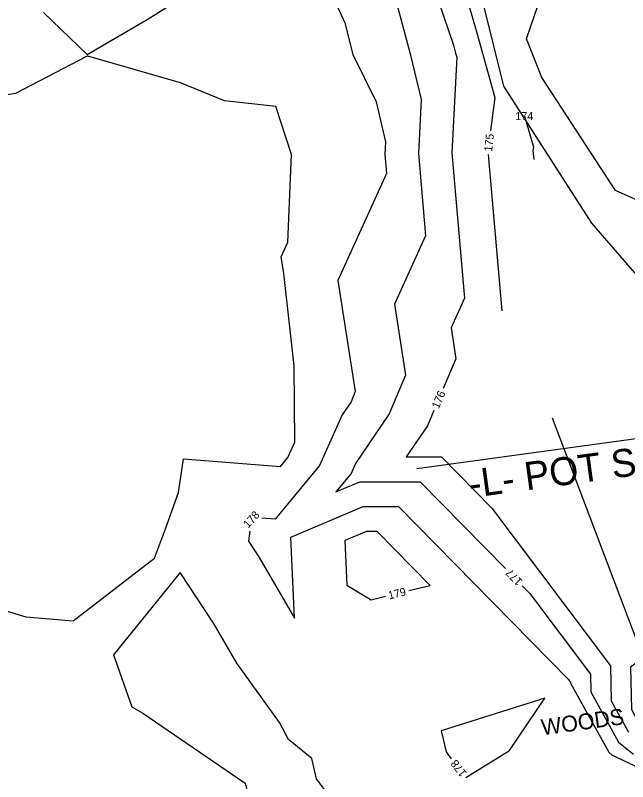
# Model space of a CAD drawing. Extents: x 2086416 to 2115205, y 575507 to 632762.
# Drawn here: x 2111202.3 to 2111355.3, y 581693.6 to 581885 of the extents above; entities that cross this region are included whole.
import ezdxf

# ---------------------------------------------------------------- set-up
doc = ezdxf.new("R2010")
doc.units = 0
for name, color, linetype in [('DTM Contours Major', 7, 'Continuous'), ('DTM Contours Major Text', 7, 'Continuous'), ('DTM Contours Minor', 7, 'Continuous'), ('DTM Contours Minor Text', 7, 'Continuous'), ('Exist Hydro Stream or Body of Water', 7, 'Continuous'), ('Exist Vegetation Woods Line', 7, 'Continuous'), ('Exist Vegetation Woods Line Text', 7, 'Continuous'), ('Prop Horizontal Alignment Station Label', 7, 'Continuous')]:
    doc.layers.add(name, color=color, linetype=linetype)

msp = doc.modelspace()

# ---------------------------------------------------------------- linework, layer by layer
at = {"layer": 'DTM Contours Major'}
for points in [[(2111294.42, 581951.65), (2111302.04, 581927.39), (2111305.43, 581920.13), (2111306.86, 581913.39), (2111309.95, 581907.16), (2111317.63, 581880.63), (2111322.13, 581864.47), (2111321.07, 581856.22)], [(2111320.43, 581850.26), (2111323.88, 581811.2)], [(2111336.48, 581784.42), (2111359.19, 581724.48), (2111356.03, 581722.18), (2111356.22, 581711.58), (2111357.93, 581708.49), (2111367.42, 581700.82), (2111367.7, 581700.69), (2111370.5, 581699.17), (2111370.16, 581701.31)]]:
    msp.add_lwpolyline(points, dxfattribs=at)
at = {"layer": 'DTM Contours Minor'}
for points in [[(2111267.74, 581979.73), (2111268.68, 581977.35), (2111273.87, 581968.84), (2111278.26, 581965.37), (2111287.18, 581945.83), (2111288.13, 581942.79), (2111297.45, 581922.87), (2111301.36, 581904.36), (2111305.53, 581895.97), (2111311.8, 581877.57), (2111312.33, 581875.57), (2111312.59, 581874.51), (2111311.38, 581850.65), (2111314.56, 581814.31), (2111311.18, 581806.9), (2111312.39, 581799.22), (2111309.24, 581791.82)], [(2111255.12, 581935.83), (2111260.16, 581925.24), (2111262.37, 581919.63), (2111267.2, 581916.59), (2111274.77, 581907.52), (2111277.54, 581898.66), (2111284.66, 581883.15), (2111286.66, 581875.21), (2111292.46, 581863.42), (2111294.84, 581853.39), (2111294.68, 581850.26), (2111295.1, 581845.49), (2111282.89, 581818.74), (2111287.27, 581791.01), (2111286.2, 581788.48), (2111283.99, 581785.23), (2111278.31, 581772.53), (2111267.27, 581759.11), (2111263.91, 581759.38)], [(2111268.74, 581824.66), (2111270.41, 581828.31), (2111271.33, 581850.23), (2111267.38, 581862.23), (2111254.62, 581863.65), (2111243.58, 581868.14), (2111220.45, 581874.8), (2111220.28, 581874.83), (2111202.41, 581865.47), (2111192.71, 581863.81), (2111182.9, 581866.81), (2111168.35, 581871.46), (2111157.17, 581875.34), (2111163.3, 581887.8), (2111160.57, 581900.16), (2111168.13, 581917.03)], [(2111292.27, 581905.43), (2111295.25, 581895.93), (2111295.93, 581894.45), (2111301, 581875.36), (2111303.71, 581863.95), (2111303.03, 581850.45), (2111304.83, 581829.9), (2111297.03, 581812.82), (2111299.83, 581795.12), (2111295.74, 581785.49), (2111287.34, 581773.08), (2111286.2, 581770.54), (2111282.44, 581765.97), (2111288.39, 581768.49), (2111303.45, 581768.49), (2111324.76, 581746.78)], [(2111209.35, 581885.74), (2111220.29, 581875.21), (2111235.29, 581883.96), (2111244.87, 581890.06), (2111253.08, 581891.47), (2111248.89, 581899.98), (2111246.81, 581901.29)], [(2111329.52, 581859.82), (2111331.49, 581853), (2111331.75, 581852.06), (2111331.65, 581851.26), (2111331.85, 581848.95)], [(2111172.65, 581747.61), (2111175.49, 581739.43), (2111189.76, 581746.49), (2111199.26, 581736.52), (2111204.94, 581734.72), (2111216.79, 581733.74), (2111237.11, 581749.36), (2111239.88, 581756.72), (2111243.14, 581765.77), (2111244.32, 581774.22), (2111268.57, 581772.28), (2111270.42, 581774.52), (2111272.15, 581778.4), (2111272.02, 581797.41), (2111269.39, 581820.52), (2111268.74, 581824.66)], [(2111306.89, 581786.29), (2111305.27, 581782.49), (2111300, 581774.7), (2111308.81, 581774.7), (2111321.39, 581761.89), (2111351, 581722.5), (2111351.15, 581713.78), (2111355.49, 581705.96)], [(2111260.91, 581756.14), (2111260.56, 581753.66), (2111263.25, 581749.57), (2111272.06, 581734.37), (2111271.17, 581754.63), (2111289.23, 581762.28), (2111298.09, 581762.28), (2111340.41, 581719.17), (2111341.02, 581718.36), (2111341.03, 581718.18), (2111350.61, 581700.9), (2111351.45, 581700.22), (2111365.39, 581693.62), (2111366.1, 581693.23), (2111372.81, 581687.77), (2111373.33, 581687.33), (2111373.12, 581686.65), (2111370.29, 581684.39), (2111374.42, 581679.53), (2111381.41, 581682.41)], [(2111292.74, 581756.06), (2111290.08, 581756.06), (2111284.68, 581753.78), (2111285.16, 581742.69), (2111291.22, 581739.02), (2111294.81, 581739.88)], [(2111300.64, 581741.29), (2111305.98, 581742.58), (2111292.74, 581756.06)], [(2111252.01, 581732.92), (2111243.5, 581745.85), (2111226.88, 581725.22), (2111231.48, 581712.27), (2111234.2, 581710.64), (2111259.76, 581693.18), (2111261.75, 581685.36), (2111258.49, 581673.26), (2111269.36, 581662.09), (2111244.24, 581668.39), (2111243.94, 581670.7), (2111236.21, 581669.26), (2111222.87, 581667.9), (2111221.36, 581667.61), (2111219.89, 581666.65), (2111218.75, 581661.3), (2111218.6, 581660), (2111219.79, 581657.23), (2111220.12, 581657.16), (2111220.04, 581657.09), (2111221.26, 581655.77), (2111227.78, 581651.56), (2111229.17, 581651.62)], [(2111328.97, 581742.5), (2111330.9, 581740.53), (2111346.01, 581720.43), (2111346.09, 581715.98), (2111353.05, 581703.43), (2111356.77, 581700.42)], [(2111235.16, 581651.86), (2111248.8, 581652.41), (2111249.48, 581653.23), (2111270, 581661.14), (2111270.74, 581661.11), (2111272.17, 581661.2), (2111281.87, 581666.23), (2111283.35, 581675.5), (2111281.36, 581689.25), (2111277.59, 581694.27), (2111276.39, 581699.32), (2111270.55, 581704.07), (2111268.32, 581708.33), (2111257.68, 581723.13), (2111252.01, 581732.92)], [(2111334.62, 581714.44), (2111308.74, 581706.23), (2111309.97, 581701), (2111311.25, 581699.31)], [(2111314.86, 581694.57), (2111325.77, 581701.36), (2111334.62, 581714.44)]]:
    msp.add_lwpolyline(points, dxfattribs=at)
at = {"layer": 'Exist Hydro Stream or Body of Water'}
msp.add_lwpolyline([(2111463, 581737.48), (2111415.11, 581766.53), (2111397.64, 581820.96), (2111352.3, 581841.23), (2111333.83, 581869.49), (2111330, 581879.12), (2111337.82, 581902), (2111329.78, 581919.05), (2111313.88, 581938.09), (2111294.11, 581978.61), (2111295.93, 582000.43), (2111293.88, 582015.55), (2111285.78, 582045.07), (2111284.37, 582067.54), (2111288.67, 582094.58), (2111287.89, 582112.99), (2111281.07, 582150.07), (2111274.06, 582190.6)], dxfattribs=at)
at = {"layer": 'Exist Vegetation Woods Line'}
msp.add_lwpolyline([(2111262.29, 582184.02), (2111265.31, 582083.43), (2111279.98, 581987.09), (2111311.55, 581918.74), (2111324.25, 581867.33), (2111346.25, 581833.12), (2111371.51, 581803.94), (2111391.8, 581769.41), (2111452.1, 581736.22)], dxfattribs=at)
at = {"layer": 'Prop Horizontal Alignment Station Label'}
msp.add_line((2111302.64, 581771.83), (2111433.3, 581789.66), dxfattribs=at)

# ---------------------------------------------------------------- texts
at = {"layer": 'DTM Contours Major Text'}
msp.add_text('175', height=2, rotation=83.9088, dxfattribs=at).set_placement((2111321.43, 581850.87))
at = {"layer": 'DTM Contours Minor Text'}
msp.add_text('174', height=2, dxfattribs=at).set_placement((2111327.24, 581858.82))
for s, rotation, p in [('176', 66.9548, (2111308.1, 581786.57)), ('178', 47.1916, (2111260.51, 581756.77)), ('177', 134.4764, (2111329.17, 581743.72)), ('179', 13.5775, (2111295.75, 581739.08)), ('178', 127.3439, (2111315.22, 581695.71))]:
    msp.add_text(s, height=2, rotation=rotation, dxfattribs=at).set_placement(p)
at = {"layer": 'Exist Vegetation Woods Line Text'}
msp.add_text('WOODS', height=4, rotation=7.771, dxfattribs=at).set_placement((2111333.99, 581705.13))
at = {"layer": 'Prop Horizontal Alignment Station Label'}
msp.add_text('-L- POT Sta. 13+81 +/-  ', height=7, rotation=7.771, dxfattribs=at).set_placement((2111316.09, 581764.43))

doc.saveas('drawing.dxf')
